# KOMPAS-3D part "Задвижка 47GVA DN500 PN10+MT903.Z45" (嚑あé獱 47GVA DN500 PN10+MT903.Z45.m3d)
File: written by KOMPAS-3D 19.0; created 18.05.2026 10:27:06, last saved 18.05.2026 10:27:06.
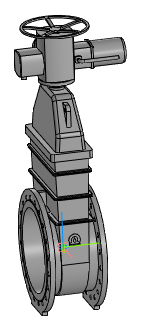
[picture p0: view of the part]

Document properties: Автор: Энергия; Полное имя файла: ..\Задвижка 47GVA DN50_DN1000+MT903.Z\Задвижка 47GVA DN500 PN10+MT903.Z45.a3d

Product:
- Part/product: Задвижка 47GVA DN500 PN10+MT903.Z45
    Масса: 924.839
  - Body: Электропривод MT903.Z45-60
      Масса: 170.293
  - Body: Задвижка 47GVA DN500 PN10 без исполнительного механизма
      Масса: 754.547

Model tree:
1. Операция без истории:1
2. Операция без истории:2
